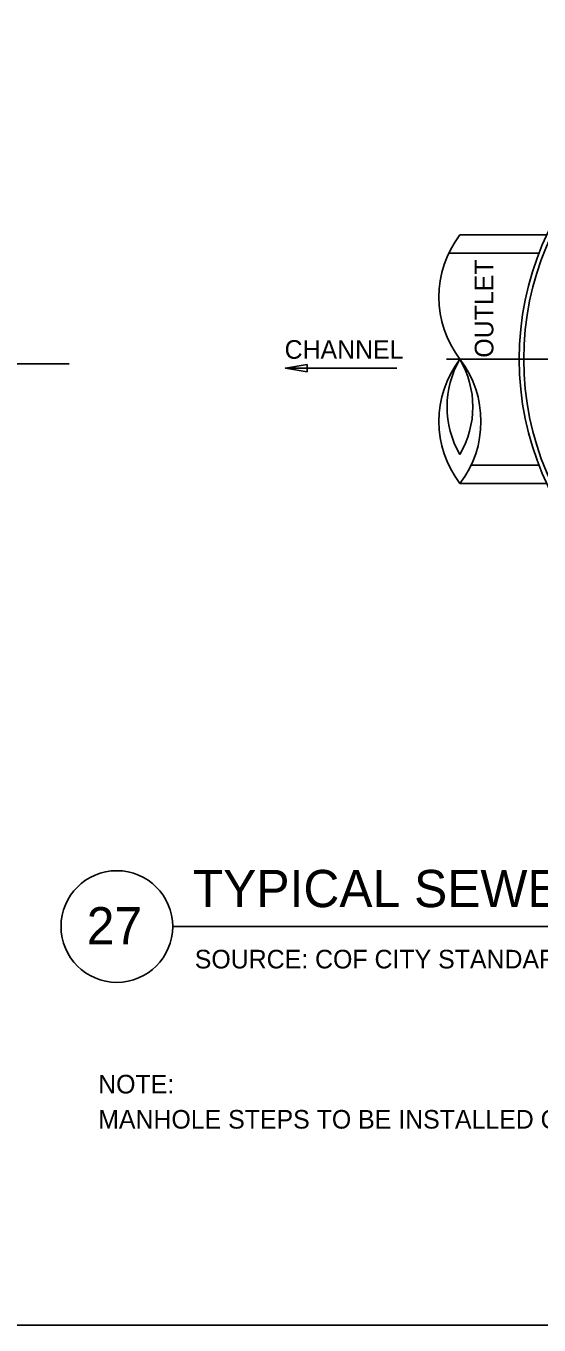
# Model space of a CAD drawing. Extents: x 6712067 to 6713867, y 1867712 to 1869162.
# Drawn here: x 6712740.8 to 6712906.2, y 1867712.3 to 1868131 of the extents above; entities that cross this region are included whole.
import ezdxf

# ---------------------------------------------------------------- set-up
doc = ezdxf.new("R2010")
doc.units = 0
for name, color, linetype in [('Default', 7, 'Continuous'), ('G-MARK', 7, 'Continuous'), ('G-TEXT', 7, 'Continuous'), ('Misc CnstDet(22)', 7, 'Continuous'), ('Nongeo Data(60)', 7, 'Continuous')]:
    doc.layers.add(name, color=color, linetype=linetype)

msp = doc.modelspace()

# ---------------------------------------------------------------- linework, layer by layer
at = {"layer": 'Default'}
msp.add_lwpolyline([(6712066.89, 1869162.31), (6713866.89, 1869162.31), (6713866.89, 1867712.31), (6712066.89, 1867712.31)], close=True, dxfattribs=at)
at = {"layer": 'G-MARK'}
msp.add_line((6712824.43, 1868020.74), (6712860.35, 1868020.74), dxfattribs=at)
at = {"layer": 'G-TEXT'}
msp.add_lwpolyline([(6712831.43, 1868019.56), (6712824.43, 1868020.74), (6712831.43, 1868021.89)], close=True, dxfattribs=at)
at = {"layer": 'Misc CnstDet(22)'}
for p, q in [((6712880.72, 1868063.69), (6712908.71, 1868063.69)), ((6712877.11, 1868057.78), (6712906.18, 1868057.78)), ((6712902.11, 1868029.23), (6712902.11, 1868029.23)), ((6712901.76, 1868027.75), (6712901.76, 1868027.75)), ((6712515.6, 1868022.15), (6712754.77, 1868022.15)), ((6712876.34, 1868023.6), (6713115.5, 1868023.6)), ((6712901.75, 1868019.53), (6712901.75, 1868019.53)), ((6712904.76, 1868007.16), (6712904.76, 1868007.16)), ((6712884.31, 1867989.43), (6712906.18, 1867989.43)), ((6712880.72, 1867983.53), (6712908.71, 1867983.53))]:
    msp.add_line(p, q, dxfattribs=at)
msp.add_lwpolyline([(6712880.72, 1868023.6), (6712880.72, 1868023.6)], dxfattribs=at)
for radius in [94.73, 93.28]:
    msp.add_circle((6712994.54, 1868023.61), radius, dxfattribs=at)
for centre, radius, start, end in [((6712906.95, 1868043.65), 33.02, 142.6308, 217.3692), ((6712906.95, 1868003.57), 33.02, 142.6308, 217.3692), ((6712906.95, 1868008.28), 30.39, 149.7116, 210.2885), ((6712854.47, 1868003.57), 33.02, 322.6308, 37.3692), ((6712854.47, 1868008.28), 30.39, 329.7116, 30.2885)]:
    msp.add_arc(centre, radius, start, end, dxfattribs=at)
at = {"layer": 'Nongeo Data(60)'}
msp.add_line((6712788.09, 1867840.76), (6713165.2, 1867840.76), dxfattribs=at)
msp.add_circle((6712770.09, 1867840.76), 18, dxfattribs=at)

# ---------------------------------------------------------------- texts
at = {"layer": 'Misc CnstDet(22)'}
msp.add_text('OUTLET', height=6, rotation=90, dxfattribs=at).set_placement((6712891.49, 1868024.11))
for s, height, p in [('CHANNEL', 6, (6712824.18, 1868023.76)), ('TYPICAL SEWER MANHOLE BASES', 12, (6712794.58, 1867847)), ('27', 12, (6712760.38, 1867835.01)), ('SOURCE: COF CITY STANDARD PLANS, FEBRUARY 2007', 6, (6712795.22, 1867827.25)), ('NOTE:', 6, (6712764.07, 1867786.95)), ('MANHOLE STEPS TO BE INSTALLED ON THE DOWNSTREAM SIDE ONLY', 6, (6712764.07, 1867775.62))]:
    msp.add_text(s, height=height, dxfattribs=at).set_placement(p)

doc.saveas('drawing.dxf')
